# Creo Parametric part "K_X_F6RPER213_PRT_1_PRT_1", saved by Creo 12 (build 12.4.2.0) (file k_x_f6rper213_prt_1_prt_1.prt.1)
Units: Custom; MM, KILOGRAM, SECS

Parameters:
  PTC_WM_ITERATION = "0"
  PTC_WM_VERSION = "-.0"
  PTC_WM_LIFECYCLE_STATE = "In Work"
  PTC_WM_LIFECYCLE = "MO_CADDocument"
  PTC_WM_CREATED_BY = "Maximilian Roepper (Z0017RMS: MO)"
  PTC_WM_CREATED_ON = "18-Sep-26 11:36:42 AM"
  PTC_WM_MODIFIED_BY = "Maximilian Roepper (Z0017RMS: MO)"
  PTC_WM_MODIFIED_ON = "18-Sep-26 11:36:46 AM"
  PDMLINKNUMBER = "PDM000071455286"
  PTC_WM_NAME = "k_x_f6rper213_prt_1_prt_1.prt"
  PTC_WM_NUMBER = "PDM000071455286"

Other parameters: WEIGHT, WEIGHT_FACTOR, WEIGHT_ADD, _MASS_TEMP, _DIFF_TEMP, MC_ERRORS, SUPPLIER

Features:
  1. coordinate system
  2. datum plane "PRT_YZ"
  3. datum plane "PRT_XY"
  4. datum plane "PRT_XZ"
  5. coordinate system
  6. datum axis
  7. datum axis
  8. datum axis
  9. coordinate system
  10. imported feature
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
Other named items: PRT, SIEMENS_MO, DRW_VIEW_ORG, PRT_X, PRT_Y, PRT_Z, CS0, ROUGH_GROB

Layers: 00_STD_CSYS-KSYS, 01_STD_PLANES-EBENEN, 02_STD_AXES-ACHSEN, 03_STD_CSYS-KSYS, 24_IMPORT_FEAT-IMPORT_KE

Surfaces: 14 plane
